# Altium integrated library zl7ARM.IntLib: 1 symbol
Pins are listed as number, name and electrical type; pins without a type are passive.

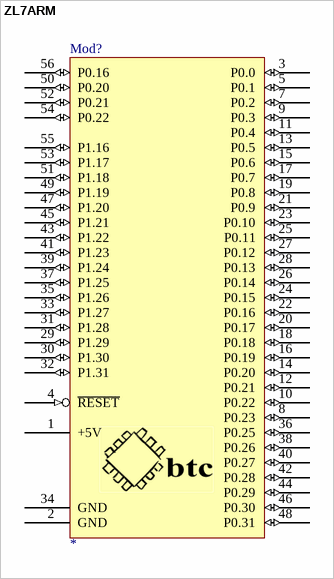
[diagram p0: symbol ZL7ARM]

## ZL7ARM
designator Mod?
www.btc.pl
footprint ZL7ARM
pins: 1 +5V (power), 2 GND (power), 3 P0.0 (io), 4 ~{RESET} (in), 5 P0.1 (io), 7 P0.2 (io), 8 P0.23 (io), 9 P0.3 (io), 10 P0.22 (io), 11 P0.4 (io), 12 P0.21 (io), 13 P0.5 (io), 14 P0.20 (io), 15 P0.6 (io), 16 P0.19 (io), 17 P0.7 (io), 18 P0.18 (io), 19 P0.8 (io), 20 P0.17 (io), 21 P0.9 (io), 22 P0.16 (io), 23 P0.10 (io), 24 P0.15 (io), 25 P0.11 (io), 26 P0.14 (io), 27 P0.12 (io), 28 P0.13 (io), 29 P1.29 (io), 30 P1.30 (io), 31 P1.28 (io), 32 P1.31 (io), 33 P1.27 (io), 34 GND (power), 35 P1.26 (io), 36 P0.25 (io), 37 P1.25 (io), 38 P0.26 (io), 39 P1.24 (io), 40 P0.27 (io), 41 P1.23 (io), 42 P0.28 (io), 43 P1.22 (io), 44 P0.29 (io), 45 P1.21 (io), 46 P0.30 (io), 47 P1.20 (io), 48 P0.31 (io), 49 P1.19 (io), 50 P0.20 (io), 51 P1.18 (io), 52 P0.21 (io), 53 P1.17 (io), 54 P0.22 (io), 55 P1.16 (io), 56 P0.16 (io)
